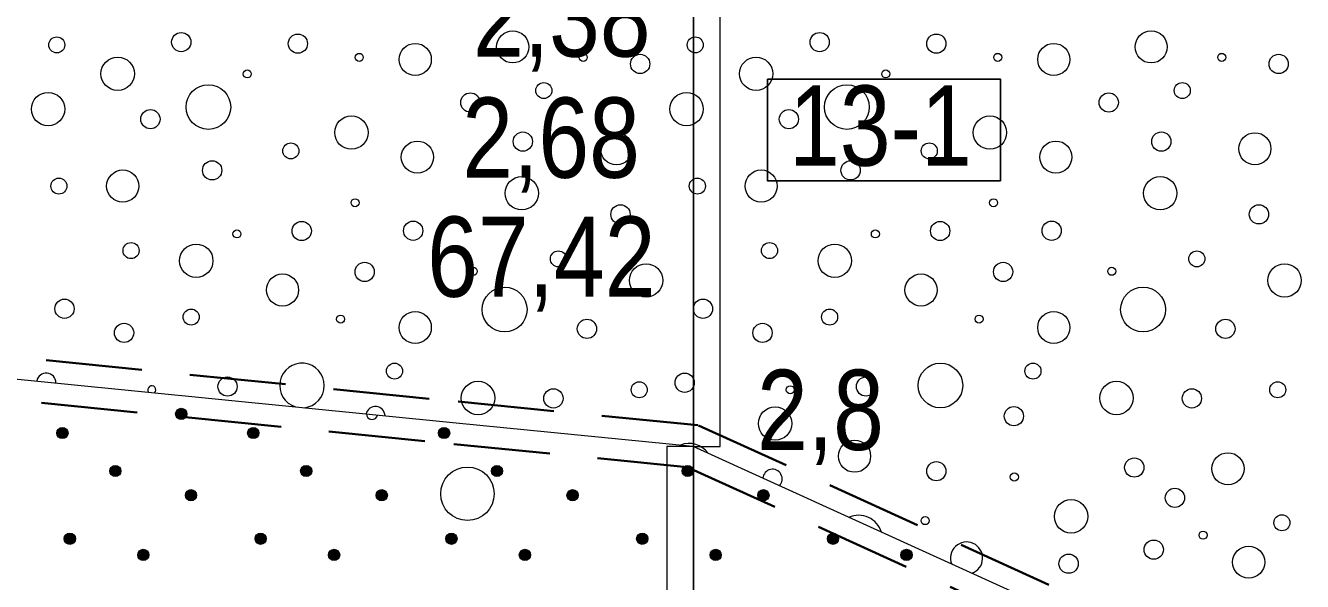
# Model space of a CAD drawing. Extents: x 640104 to 640970, y 6442278 to 6442689.
# Drawn here: x 640217.85 to 640265.58, y 6442408.6 to 6442429.39 of the extents above; entities that cross this region are included whole.
import ezdxf
from ezdxf.enums import TextEntityAlignment as Align

# ---------------------------------------------------------------- set-up
doc = ezdxf.new("R2010")
doc.units = 0
doc.header["$LTSCALE"] = 1.2
doc.linetypes.add('MEDIUM_DASHED', pattern=[4.5, 3, -1.5])
for name, color, linetype, lineweight in [('31', 7, 'Continuous', 13), ('32', 7, 'Continuous', 25), ('33', 7, 'Continuous', 13), ('35', 7, 'Continuous', 35), ('41', 7, 'Continuous', 13), ('44', 7, 'Continuous', 13), ('47', 7, 'Continuous', 13)]:
    doc.layers.add(name, color=color, linetype=linetype, lineweight=lineweight)

msp = doc.modelspace()

# ---------------------------------------------------------------- hatches: boundary and pattern name
at = {"layer": '44'}
for points in [[(640223.878, 6442414.868, 1), (640223.458, 6442414.868, 1)], [(640219.437, 6442414.153, 1), (640219.017, 6442414.153, 1)], [(640226.57, 6442414.153, 1), (640226.15, 6442414.153, 1)], [(640233.703, 6442414.153, 1), (640233.283, 6442414.153, 1)], [(640221.415, 6442412.734, 1), (640220.995, 6442412.734, 1)], [(640228.548, 6442412.734, 1), (640228.128, 6442412.734, 1)], [(640235.681, 6442412.734, 1), (640235.261, 6442412.734, 1)], [(640242.814, 6442412.734, 1), (640242.394, 6442412.734, 1)], [(640224.242, 6442411.826, 1), (640223.822, 6442411.826, 1)], [(640231.375, 6442411.826, 1), (640230.955, 6442411.826, 1)], [(640238.508, 6442411.826, 1), (640238.088, 6442411.826, 1)], [(640245.641, 6442411.826, 1), (640245.221, 6442411.826, 1)], [(640219.712, 6442410.2, 1), (640219.292, 6442410.2, 1)], [(640226.845, 6442410.2, 1), (640226.425, 6442410.2, 1)], [(640233.978, 6442410.2, 1), (640233.558, 6442410.2, 1)], [(640241.111, 6442410.2, 1), (640240.691, 6442410.2, 1)], [(640248.244, 6442410.2, 1), (640247.824, 6442410.2, 1)], [(640222.459, 6442409.595, 1), (640222.039, 6442409.595, 1)], [(640229.592, 6442409.595, 1), (640229.172, 6442409.595, 1)], [(640236.725, 6442409.595, 1), (640236.305, 6442409.595, 1)], [(640243.858, 6442409.595, 1), (640243.438, 6442409.595, 1)], [(640250.991, 6442409.595, 1), (640250.571, 6442409.595, 1)]]:
    msp.add_hatch(color=256, dxfattribs=at).paths.add_polyline_path(points)

# ---------------------------------------------------------------- linework, layer by layer
at = {"layer": '31'}
msp.add_lwpolyline([(640139.08, 6442423.82), (640151.96, 6442423.75), (640173.66, 6442421.26), (640213.16, 6442416.61), (640233.94, 6442414.53), (640242.79, 6442413.66), (640295.17, 6442389.83), (640328.15, 6442387.74), (640358.78, 6442385.66), (640377.96, 6442384.87), (640391.41, 6442383.72), (640397.31, 6442383.01), (640414.42, 6442381.45)], dxfattribs=at)
at = {"layer": '32'}
msp.add_line((640242.82, 6442441.65), (640242.82, 6442376.65), dxfattribs=at)
at = {"layer": '33'}
for points in [[(640243.82, 6442413.65), (640243.82, 6442438.65), (640242.91, 6442438.65), (640242.91, 6442438.65), (640242.82, 6442438.62), (640242.82, 6442413.66), (640242.82, 6442413.65)], [(640241.82, 6442413.65), (640241.82, 6442382), (640242.69, 6442381.65), (640242.81, 6442381.65), (640242.82, 6442381.65), (640242.82, 6442413.65), (640242.8, 6442413.65), (640242.79, 6442413.65)]]:
    msp.add_lwpolyline(points, close=True, dxfattribs=at)
at = {"layer": '33', "lineweight": 25}
msp.add_lwpolyline([(640245.58, 6442427.39), (640254.29, 6442427.39), (640254.29, 6442423.59), (640245.58, 6442423.59)], close=True, dxfattribs=at)
at = {"layer": '35', "linetype": 'MEDIUM_DASHED'}
for points in [[(640153.52, 6442424.38), (640173.75, 6442422.06), (640213.24, 6442417.41), (640234.02, 6442415.33), (640243, 6442414.44), (640295.36, 6442390.62), (640328.2, 6442388.54), (640358.82, 6442386.46), (640378.01, 6442385.67), (640391.49, 6442384.52), (640397.4, 6442383.81), (640411.83, 6442382.49)], [(640153.52, 6442422.77), (640173.56, 6442420.47), (640213.07, 6442415.82), (640233.86, 6442413.74), (640242.58, 6442412.88), (640294.97, 6442389.04), (640328.09, 6442386.94), (640358.73, 6442384.86), (640377.91, 6442384.07), (640391.32, 6442382.92), (640397.23, 6442382.22), (640405.71, 6442381.44)]]:
    msp.add_lwpolyline(points, dxfattribs=at)
at = {"layer": '41'}
for centre, radius in [((640219.015, 6442428.667), 0.3), ((640223.667, 6442428.772), 0.36), ((640228.028, 6442428.715), 0.36), ((640236.059, 6442428.592), 0.6), ((640242.884, 6442428.667), 0.3), ((640247.536, 6442428.772), 0.36), ((640251.897, 6442428.715), 0.36), ((640259.928, 6442428.592), 0.6), ((640230.323, 6442428.202), 0.15), ((640232.417, 6442428.124), 0.6), ((640238.696, 6442428.202), 0.15), ((640254.192, 6442428.202), 0.15), ((640256.286, 6442428.124), 0.6), ((640262.565, 6442428.202), 0.15), ((640221.291, 6442427.586), 0.624), ((640240.825, 6442427.955), 0.36), ((640245.16, 6442427.586), 0.624), ((640264.694, 6442427.955), 0.36), ((640226.135, 6442427.581), 0.15), ((640250.004, 6442427.581), 0.15), ((640224.683, 6442426.343), 0.835), ((640237.223, 6442426.96), 0.3), ((640248.552, 6442426.343), 0.835), ((640261.092, 6442426.96), 0.3), ((640218.689, 6442426.266), 0.624), ((640234.474, 6442426.514), 0.36), ((640242.558, 6442426.266), 0.624), ((640258.343, 6442426.514), 0.36), ((640222.515, 6442425.89), 0.36), ((640230.029, 6442425.388), 0.624), ((640246.384, 6442425.89), 0.36), ((640253.898, 6442425.388), 0.624), ((640227.764, 6442424.704), 0.3), ((640232.495, 6442424.473), 0.6), ((640236.438, 6442425.052), 0.36), ((640239.938, 6442424.785), 0.6), ((640251.633, 6442424.704), 0.3), ((640256.364, 6442424.473), 0.6), ((640260.307, 6442425.052), 0.36), ((640263.807, 6442424.785), 0.6), ((640224.822, 6442423.976), 0.36), ((640248.691, 6442423.976), 0.36), ((640219.093, 6442423.387), 0.3), ((640221.479, 6442423.39), 0.6), ((640236.397, 6442423.119), 0.624), ((640242.962, 6442423.387), 0.3), ((640245.348, 6442423.39), 0.6), ((640260.266, 6442423.119), 0.624), ((640230.167, 6442422.766), 0.15), ((640240.088, 6442422.331), 0.36), ((640254.036, 6442422.766), 0.15), ((640263.957, 6442422.331), 0.36), ((640225.748, 6442421.599), 0.15), ((640228.171, 6442421.709), 0.36), ((640232.338, 6442421.719), 0.36), ((640249.617, 6442421.599), 0.15), ((640252.04, 6442421.709), 0.36), ((640256.207, 6442421.719), 0.36), ((640221.791, 6442420.975), 0.3), ((640224.23, 6442420.595), 0.624), ((640245.66, 6442420.975), 0.3), ((640248.099, 6442420.595), 0.624), ((640237.766, 6442420.666), 0.3), ((640261.635, 6442420.666), 0.3), ((640230.524, 6442420.178), 0.36), ((640234.586, 6442420.201), 0.15), ((640241.048, 6442419.859), 0.624), ((640254.393, 6442420.178), 0.36), ((640258.455, 6442420.201), 0.15), ((640264.917, 6442419.859), 0.624), ((640227.455, 6442419.502), 0.6), ((640251.324, 6442419.502), 0.6), ((640235.756, 6442418.772), 0.838), ((640259.625, 6442418.772), 0.838), ((640219.303, 6442418.801), 0.36), ((640224.038, 6442418.491), 0.3), ((640243.172, 6442418.801), 0.36), ((640247.907, 6442418.491), 0.3), ((640229.624, 6442418.413), 0.15), ((640232.417, 6442418.101), 0.6), ((640238.835, 6442418.05), 0.36), ((640253.493, 6442418.413), 0.15), ((640256.286, 6442418.101), 0.6), ((640262.704, 6442418.05), 0.36), ((640221.53, 6442417.898), 0.36), ((640245.399, 6442417.898), 0.36), ((640231.64, 6442416.469), 0.3), ((640242.488, 6442416.035), 0.36), ((640252.051, 6442415.931), 0.834), ((640255.509, 6442416.469), 0.3), ((640225.399, 6442415.892), 0.36), ((640234.762, 6442415.463), 0.624), ((640240.79, 6442415.77), 0.3), ((640246.437, 6442415.77), 0.15), ((640249.268, 6442415.892), 0.36), ((640258.631, 6442415.463), 0.624), ((640264.659, 6442415.77), 0.3), ((640237.581, 6442415.448), 0.36), ((640261.45, 6442415.448), 0.36), ((640245.868, 6442414.506), 0.624), ((640254.796, 6442414.783), 0.36), ((640248.84, 6442413.286), 0.6), ((640251.897, 6442412.725), 0.36), ((640259.297, 6442412.862), 0.36), ((640262.799, 6442412.818), 0.6), ((640254.813, 6442412.509), 0.15), ((640256.935, 6442411.038), 0.624), ((640260.816, 6442411.73), 0.36), ((640251.477, 6442410.877), 0.15), ((640264.815, 6442410.799), 0.3), ((640261.869, 6442410.334), 0.15), ((640260.024, 6442409.793), 0.36), ((640263.573, 6442409.323), 0.6), ((640256.842, 6442409.267), 0.36)]:
    msp.add_circle(centre, radius, dxfattribs=at)
for centre, radius, start, end in [((640218.619, 6442416.035), 0.36, 358.935, 169.6484), ((640228.182, 6442415.931), 0.834, 275.234, 253.3494), ((640222.568, 6442415.77), 0.15, 312.9713, 215.6121), ((640230.927, 6442414.783), 0.36, 2.4269, 166.1565), ((640242.648, 6442412.874), 0.889, 35.9032, 110.8996), ((640245.773, 6442412.438), 0.36, 315.234, 175.8361), ((640248.991, 6442410.184), 0.893, 17.2118, 113.8584), ((640253.028, 6442409.479), 0.6, 289.0162, 202.0539)]:
    msp.add_arc(centre, radius, start, end, dxfattribs=at)
at = {"layer": '44'}
for centre in [(640223.668, 6442414.868), (640219.227, 6442414.153), (640226.36, 6442414.153), (640233.493, 6442414.153), (640221.205, 6442412.734), (640228.338, 6442412.734), (640235.471, 6442412.734), (640242.604, 6442412.734), (640224.032, 6442411.826), (640231.165, 6442411.826), (640238.298, 6442411.826), (640245.431, 6442411.826), (640219.502, 6442410.2), (640226.635, 6442410.2), (640233.768, 6442410.2), (640240.901, 6442410.2), (640248.034, 6442410.2), (640222.249, 6442409.595), (640229.382, 6442409.595), (640236.515, 6442409.595), (640243.648, 6442409.595), (640250.781, 6442409.595)]:
    msp.add_circle(centre, 0.21, dxfattribs=at)
msp.add_arc((640230.801, 6442414.868), 0.21, 180.1214, 348.462, dxfattribs=at)
at = {"layer": '47'}
msp.add_circle((640234.367, 6442411.881), 1, dxfattribs=at)

# ---------------------------------------------------------------- texts
at = {"layer": '32', "width": 0.85}
msp.add_text('2,8', height=3, dxfattribs=at).set_placement((640247.565, 6442413.52), align=Align.CENTER)
at = {"layer": '33', "width": 0.85}
for s, p in [('2,38', (640237.895, 6442428.23)), ('13-1', (640249.805, 6442424.15)), ('2,68', (640237.495, 6442423.7)), ('67,42', (640237.13, 6442419.25))]:
    msp.add_text(s, height=3, dxfattribs=at).set_placement(p, align=Align.CENTER)

doc.saveas('drawing.dxf')
